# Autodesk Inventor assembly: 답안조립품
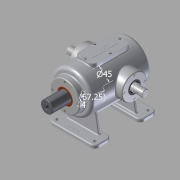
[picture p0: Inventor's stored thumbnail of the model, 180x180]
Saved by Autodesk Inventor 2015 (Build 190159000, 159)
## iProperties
Created: 2016-02
Part Number: 답안조립품
Document SubType Name: Assembly
Designer: Administrator
Mass: 8191.31 g
Surface Area: 4241.85 cm^2
Volume: 1855.5 cm^3
Density: 4.4146 g/cm^3
Author: Administrator
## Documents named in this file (15)
- C:\Users\Administrator\Desktop\360220V1008\답안조립품.iam
- C:\Users\Administrator\Desktop\360220V1008\본체.ipt
- C:\Users\Administrator\Desktop\360220V1008\상부커버.ipt
- C:\Users\Administrator\Desktop\360220V1008\육각머리볼트 M4.ipt
- C:\Users\Administrator\Desktop\360220V1008\축 커버.ipt
- C:\Users\Administrator\Desktop\360220V1008\볼트 M4x0.7.ipt
- C:\Users\Administrator\Desktop\360220V1008\오일실.ipt
- 오일실.ipt
- C:\Users\Administrator\Desktop\360220V1008\베어링 6205.ipt
- 베어링 6205.ipt
- C:\Users\Administrator\Desktop\360220V1008\편심축.ipt
- C:\Users\Administrator\Desktop\360220V1008\슬라이드 커버.ipt
- C:\Users\Administrator\Desktop\360220V1008\부시.ipt
- C:\Users\Administrator\Desktop\360220V1008\슬라이드.ipt
- C:\Users\Administrator\Desktop\360220V1008\가변스프링.ipt
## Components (13 placed, 2 different names)
1. 가변스프링:1
2. M4x0.7:1
3. M4x0.7:2
4. M4x0.7:3
5. M4x0.7:4
6. M4x0.7:5
7. M4x0.7:6
8. M4x0.7:7
9. M4x0.7:8
10. M4x0.7:9
11. M4x0.7:10
12. M4x0.7:11
13. M4x0.7:12
